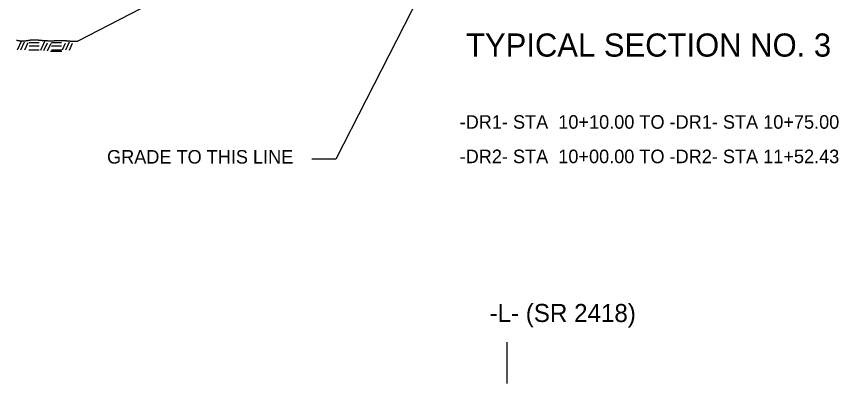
# Model space of a CAD drawing. Extents: x 1542177 to 1542464, y 45134 to 45344.
# Drawn here: x 1542275.51 to 1542311.92, y 45178.07 to 45194.34 of the extents above; entities that cross this region are included whole.
import ezdxf

# ---------------------------------------------------------------- set-up
doc = ezdxf.new("R2010")
doc.units = 0
for name, color, linetype in [('Default', 7, 'Continuous'), ('Old_Level_1', 7, 'Continuous'), ('Old_Level_2', 7, 'Continuous')]:
    doc.layers.add(name, color=color, linetype=linetype)

msp = doc.modelspace()

# ---------------------------------------------------------------- linework, layer by layer
at = {"layer": 'Default'}
for p, q in [((1542278.251, 45193.26), (1542289.419, 45199.047)), ((1542275.745, 45193.258), (1542275.554, 45192.844)), ((1542275.863, 45193.203), (1542275.698, 45192.854)), ((1542276.016, 45193.172), (1542275.868, 45192.853)), ((1542276.072, 45193.189), (1542276.519, 45193.189)), ((1542276.072, 45193.037), (1542276.52, 45193.036)), ((1542276.779, 45193.255), (1542276.582, 45192.834)), ((1542276.874, 45193.157), (1542276.718, 45192.819)), ((1542277.033, 45193.138), (1542276.877, 45192.8)), ((1542277.062, 45193.038), (1542277.513, 45193.037)), ((1542277.063, 45193.189), (1542277.513, 45193.188)), ((1542277.679, 45193.142), (1542277.544, 45192.853)), ((1542277.846, 45193.201), (1542277.682, 45192.846)), ((1542277.985, 45193.137), (1542277.843, 45192.833)), ((1542276.071, 45192.863), (1542276.519, 45192.863)), ((1542277.026, 45192.8), (1542277.521, 45192.8)), ((1542277.063, 45192.861), (1542277.512, 45192.862)), ((1542297.238, 45179.91), (1542297.238, 45178.068))]:
    msp.add_line(p, q, dxfattribs=at)
msp.add_open_spline([(1542275.515, 45193.287), (1542275.516, 45193.288), (1542275.516, 45193.289), (1542275.517, 45193.29), (1542275.52, 45193.291), (1542275.522, 45193.289), (1542275.524, 45193.289), (1542275.527, 45193.289), (1542275.529, 45193.29), (1542275.532, 45193.29), (1542275.534, 45193.29), (1542275.536, 45193.288), (1542275.538, 45193.288), (1542275.541, 45193.287), (1542275.543, 45193.286), (1542275.546, 45193.286), (1542275.548, 45193.285), (1542275.551, 45193.285), (1542275.553, 45193.284), (1542275.555, 45193.284), (1542275.557, 45193.283), (1542275.559, 45193.282), (1542275.562, 45193.282), (1542275.565, 45193.283), (1542275.568, 45193.282), (1542275.57, 45193.282), (1542275.572, 45193.281), (1542275.575, 45193.28), (1542275.577, 45193.28), (1542275.58, 45193.281), (1542275.582, 45193.281), (1542275.585, 45193.28), (1542275.587, 45193.279), (1542275.59, 45193.279), (1542275.592, 45193.278), (1542275.594, 45193.277), (1542275.596, 45193.277), (1542275.599, 45193.276), (1542275.602, 45193.276), (1542275.604, 45193.276), (1542275.606, 45193.275), (1542275.609, 45193.276), (1542275.611, 45193.275), (1542275.613, 45193.275), (1542275.616, 45193.274), (1542275.618, 45193.273), (1542275.621, 45193.273), (1542275.623, 45193.272), (1542275.626, 45193.272), (1542275.628, 45193.271), (1542275.63, 45193.272), (1542275.633, 45193.271), (1542275.635, 45193.271), (1542275.638, 45193.27), (1542275.64, 45193.269), (1542275.642, 45193.269), (1542275.644, 45193.268), (1542275.647, 45193.268), (1542275.65, 45193.267), (1542275.653, 45193.269), (1542275.657, 45193.268), (1542275.659, 45193.268), (1542275.661, 45193.266), (1542275.663, 45193.266), (1542275.667, 45193.266), (1542275.671, 45193.266), (1542275.675, 45193.266), (1542275.677, 45193.266), (1542275.679, 45193.267), (1542275.681, 45193.266), (1542275.685, 45193.266), (1542275.689, 45193.265), (1542275.692, 45193.265), (1542275.694, 45193.265), (1542275.697, 45193.264), (1542275.699, 45193.264), (1542275.702, 45193.264), (1542275.706, 45193.265), (1542275.709, 45193.265), (1542275.712, 45193.265), (1542275.715, 45193.265), (1542275.717, 45193.264), (1542275.721, 45193.264), (1542275.725, 45193.264), (1542275.728, 45193.264), (1542275.732, 45193.264), (1542275.735, 45193.264), (1542275.739, 45193.264), (1542275.741, 45193.264), (1542275.744, 45193.265), (1542275.746, 45193.265), (1542275.749, 45193.265), (1542275.751, 45193.264), (1542275.753, 45193.264), (1542275.757, 45193.264), (1542275.76, 45193.264), (1542275.763, 45193.265), (1542275.767, 45193.265), (1542275.771, 45193.265), (1542275.775, 45193.265), (1542275.777, 45193.265), (1542275.78, 45193.264), (1542275.782, 45193.264), (1542275.785, 45193.264), (1542275.789, 45193.264), (1542275.792, 45193.265), (1542275.795, 45193.265), (1542275.798, 45193.265), (1542275.801, 45193.264), (1542275.803, 45193.264), (1542275.805, 45193.263), (1542275.807, 45193.263), (1542275.809, 45193.263), (1542275.812, 45193.264), (1542275.814, 45193.264), (1542275.816, 45193.264), (1542275.818, 45193.264), (1542275.82, 45193.264), (1542275.823, 45193.264), (1542275.825, 45193.264), (1542275.827, 45193.264), (1542275.83, 45193.264), (1542275.832, 45193.264), (1542275.835, 45193.264), (1542275.838, 45193.264), (1542275.84, 45193.264), (1542275.843, 45193.264), (1542275.845, 45193.264), (1542275.847, 45193.264), (1542275.849, 45193.264), (1542275.851, 45193.263), (1542275.853, 45193.264), (1542275.856, 45193.264), (1542275.86, 45193.264), (1542275.864, 45193.264), (1542275.868, 45193.264), (1542275.87, 45193.264), (1542275.873, 45193.264), (1542275.875, 45193.264), (1542275.877, 45193.264), (1542275.878, 45193.264), (1542275.88, 45193.264), (1542275.884, 45193.264), (1542275.888, 45193.265), (1542275.892, 45193.266), (1542275.895, 45193.266), (1542275.897, 45193.266), (1542275.899, 45193.267), (1542275.903, 45193.267), (1542275.906, 45193.265), (1542275.909, 45193.266), (1542275.913, 45193.266), (1542275.918, 45193.268), (1542275.922, 45193.268), (1542275.925, 45193.268), (1542275.928, 45193.267), (1542275.932, 45193.268), (1542275.935, 45193.268), (1542275.939, 45193.269), (1542275.943, 45193.269), (1542275.946, 45193.27), (1542275.949, 45193.271), (1542275.952, 45193.272), (1542275.956, 45193.272), (1542275.96, 45193.271), (1542275.963, 45193.272), (1542275.966, 45193.272), (1542275.968, 45193.272), (1542275.97, 45193.273), (1542275.973, 45193.273), (1542275.975, 45193.274), (1542275.978, 45193.275), (1542275.982, 45193.276), (1542275.986, 45193.274), (1542275.99, 45193.275), (1542275.992, 45193.275), (1542275.994, 45193.276), (1542275.997, 45193.276), (1542275.999, 45193.277), (1542276.001, 45193.278), (1542276.004, 45193.278), (1542276.006, 45193.278), (1542276.008, 45193.278), (1542276.01, 45193.279), (1542276.016, 45193.279), (1542276.021, 45193.279), (1542276.027, 45193.28), (1542276.03, 45193.281), (1542276.032, 45193.281), (1542276.035, 45193.282), (1542276.037, 45193.283), (1542276.04, 45193.283), (1542276.042, 45193.284), (1542276.044, 45193.285), (1542276.047, 45193.283), (1542276.049, 45193.284), (1542276.053, 45193.284), (1542276.056, 45193.286), (1542276.06, 45193.287), (1542276.063, 45193.287), (1542276.065, 45193.287), (1542276.068, 45193.287), (1542276.071, 45193.288), (1542276.074, 45193.291), (1542276.077, 45193.291), (1542276.08, 45193.292), (1542276.082, 45193.291), (1542276.085, 45193.291), (1542276.087, 45193.292), (1542276.089, 45193.292), (1542276.092, 45193.293), (1542276.094, 45193.294), (1542276.096, 45193.294), (1542276.099, 45193.295), (1542276.102, 45193.296), (1542276.104, 45193.296), (1542276.107, 45193.297), (1542276.11, 45193.297), (1542276.114, 45193.297), (1542276.117, 45193.298), (1542276.12, 45193.298), (1542276.122, 45193.298), (1542276.125, 45193.298), (1542276.127, 45193.298), (1542276.128, 45193.3), (1542276.13, 45193.3), (1542276.133, 45193.3), (1542276.136, 45193.3), (1542276.139, 45193.3), (1542276.141, 45193.3), (1542276.144, 45193.3), (1542276.146, 45193.3), (1542276.149, 45193.3), (1542276.153, 45193.301), (1542276.157, 45193.301), (1542276.159, 45193.302), (1542276.162, 45193.301), (1542276.164, 45193.301), (1542276.166, 45193.302), (1542276.168, 45193.303), (1542276.17, 45193.304), (1542276.174, 45193.304), (1542276.178, 45193.303), (1542276.182, 45193.303), (1542276.184, 45193.303), (1542276.187, 45193.303), (1542276.189, 45193.304), (1542276.191, 45193.304), (1542276.193, 45193.305), (1542276.195, 45193.305), (1542276.198, 45193.305), (1542276.2, 45193.305), (1542276.203, 45193.305), (1542276.205, 45193.305), (1542276.207, 45193.305), (1542276.209, 45193.305), (1542276.212, 45193.305), (1542276.214, 45193.305), (1542276.217, 45193.305), (1542276.219, 45193.305), (1542276.221, 45193.305), (1542276.223, 45193.305), (1542276.226, 45193.305), (1542276.229, 45193.307), (1542276.232, 45193.307), (1542276.234, 45193.307), (1542276.236, 45193.307), (1542276.238, 45193.307), (1542276.241, 45193.307), (1542276.243, 45193.307), (1542276.246, 45193.307), (1542276.248, 45193.307), (1542276.25, 45193.307), (1542276.251, 45193.307), (1542276.256, 45193.307), (1542276.26, 45193.307), (1542276.265, 45193.307), (1542276.269, 45193.307), (1542276.273, 45193.307), (1542276.277, 45193.307), (1542276.28, 45193.307), (1542276.282, 45193.306), (1542276.285, 45193.306), (1542276.292, 45193.306), (1542276.299, 45193.307), (1542276.306, 45193.307), (1542276.308, 45193.307), (1542276.311, 45193.307), (1542276.313, 45193.307), (1542276.315, 45193.307), (1542276.317, 45193.307), (1542276.32, 45193.307), (1542276.322, 45193.307), (1542276.324, 45193.307), (1542276.327, 45193.307), (1542276.329, 45193.307), (1542276.332, 45193.307), (1542276.335, 45193.307), (1542276.338, 45193.307), (1542276.342, 45193.307), (1542276.346, 45193.307), (1542276.348, 45193.306), (1542276.351, 45193.306), (1542276.354, 45193.306), (1542276.356, 45193.306), (1542276.358, 45193.307), (1542276.36, 45193.307), (1542276.363, 45193.307), (1542276.365, 45193.306), (1542276.367, 45193.306), (1542276.37, 45193.306), (1542276.372, 45193.307), (1542276.374, 45193.307), (1542276.377, 45193.307), (1542276.379, 45193.306), (1542276.381, 45193.306), (1542276.384, 45193.306), (1542276.386, 45193.307), (1542276.388, 45193.307), (1542276.39, 45193.307), (1542276.392, 45193.307), (1542276.394, 45193.307), (1542276.398, 45193.307), (1542276.402, 45193.306), (1542276.405, 45193.306), (1542276.408, 45193.305), (1542276.411, 45193.306), (1542276.413, 45193.305), (1542276.416, 45193.305), (1542276.418, 45193.305), (1542276.42, 45193.305), (1542276.423, 45193.305), (1542276.425, 45193.306), (1542276.427, 45193.305), (1542276.429, 45193.305), (1542276.432, 45193.303), (1542276.434, 45193.303), (1542276.437, 45193.303), (1542276.439, 45193.303), (1542276.442, 45193.303), (1542276.444, 45193.303), (1542276.447, 45193.303), (1542276.449, 45193.303), (1542276.453, 45193.303), (1542276.456, 45193.303), (1542276.46, 45193.303), (1542276.462, 45193.303), (1542276.465, 45193.302), (1542276.467, 45193.301), (1542276.469, 45193.301), (1542276.472, 45193.301), (1542276.474, 45193.301), (1542276.476, 45193.301), (1542276.478, 45193.3), (1542276.481, 45193.299), (1542276.496, 45193.297), (1542276.512, 45193.295), (1542276.527, 45193.294), (1542276.529, 45193.294), (1542276.532, 45193.294), (1542276.534, 45193.294), (1542276.537, 45193.294), (1542276.539, 45193.292), (1542276.542, 45193.292), (1542276.544, 45193.292), (1542276.546, 45193.292), (1542276.548, 45193.292), (1542276.55, 45193.292), (1542276.553, 45193.293), (1542276.555, 45193.293), (1542276.558, 45193.293), (1542276.56, 45193.291), (1542276.563, 45193.291), (1542276.565, 45193.291), (1542276.567, 45193.29), (1542276.57, 45193.29), (1542276.576, 45193.29), (1542276.582, 45193.291), (1542276.588, 45193.29), (1542276.59, 45193.29), (1542276.593, 45193.289), (1542276.595, 45193.289), (1542276.597, 45193.289), (1542276.6, 45193.289), (1542276.602, 45193.289), (1542276.605, 45193.288), (1542276.607, 45193.287), (1542276.61, 45193.287), (1542276.618, 45193.286), (1542276.626, 45193.286), (1542276.634, 45193.285), (1542276.641, 45193.285), (1542276.648, 45193.284), (1542276.655, 45193.284), (1542276.658, 45193.283), (1542276.662, 45193.283), (1542276.666, 45193.282), (1542276.67, 45193.281), (1542276.673, 45193.281), (1542276.677, 45193.28), (1542276.679, 45193.28), (1542276.682, 45193.28), (1542276.685, 45193.28), (1542276.687, 45193.28), (1542276.689, 45193.278), (1542276.692, 45193.278), (1542276.694, 45193.278), (1542276.696, 45193.278), (1542276.698, 45193.278), (1542276.7, 45193.278), (1542276.703, 45193.277), (1542276.705, 45193.277), (1542276.709, 45193.276), (1542276.713, 45193.276), (1542276.716, 45193.276), (1542276.719, 45193.276), (1542276.721, 45193.275), (1542276.724, 45193.275), (1542276.727, 45193.275), (1542276.729, 45193.274), (1542276.732, 45193.274), (1542276.738, 45193.274), (1542276.743, 45193.275), (1542276.749, 45193.275), (1542276.753, 45193.274), (1542276.756, 45193.273), (1542276.76, 45193.273), (1542276.762, 45193.273), (1542276.765, 45193.273), (1542276.767, 45193.273), (1542276.773, 45193.273), (1542276.778, 45193.273), (1542276.784, 45193.273), (1542276.786, 45193.273), (1542276.788, 45193.272), (1542276.791, 45193.272), (1542276.793, 45193.272), (1542276.795, 45193.271), (1542276.798, 45193.271), (1542276.8, 45193.271), (1542276.803, 45193.271), (1542276.805, 45193.271), (1542276.811, 45193.271), (1542276.817, 45193.271), (1542276.823, 45193.271), (1542276.826, 45193.271), (1542276.828, 45193.271), (1542276.83, 45193.271), (1542276.833, 45193.271), (1542276.835, 45193.269), (1542276.838, 45193.269), (1542276.841, 45193.269), (1542276.843, 45193.269), (1542276.845, 45193.269), (1542276.851, 45193.269), (1542276.857, 45193.269), (1542276.863, 45193.269), (1542276.865, 45193.269), (1542276.868, 45193.269), (1542276.87, 45193.269), (1542276.873, 45193.269), (1542276.875, 45193.269), (1542276.878, 45193.269), (1542276.884, 45193.269), (1542276.889, 45193.268), (1542276.894, 45193.267), (1542276.896, 45193.267), (1542276.899, 45193.267), (1542276.901, 45193.267), (1542276.906, 45193.267), (1542276.91, 45193.267), (1542276.915, 45193.267), (1542276.918, 45193.267), (1542276.921, 45193.268), (1542276.924, 45193.268), (1542276.93, 45193.267), (1542276.936, 45193.267), (1542276.942, 45193.267), (1542276.95, 45193.267), (1542276.959, 45193.267), (1542276.967, 45193.267), (1542276.973, 45193.267), (1542276.979, 45193.265), (1542276.985, 45193.265), (1542276.987, 45193.265), (1542276.989, 45193.265), (1542276.99, 45193.265), (1542276.993, 45193.265), (1542276.996, 45193.266), (1542276.998, 45193.266), (1542277.004, 45193.266), (1542277.011, 45193.265), (1542277.017, 45193.265), (1542277.019, 45193.265), (1542277.021, 45193.266), (1542277.023, 45193.266), (1542277.026, 45193.266), (1542277.028, 45193.263), (1542277.03, 45193.263), (1542277.033, 45193.263), (1542277.035, 45193.263), (1542277.038, 45193.263), (1542277.04, 45193.263), (1542277.042, 45193.263), (1542277.044, 45193.263), (1542277.047, 45193.263), (1542277.049, 45193.263), (1542277.052, 45193.263), (1542277.054, 45193.263), (1542277.056, 45193.262), (1542277.059, 45193.262), (1542277.062, 45193.261), (1542277.065, 45193.261), (1542277.067, 45193.261), (1542277.07, 45193.262), (1542277.072, 45193.262), (1542277.074, 45193.262), (1542277.076, 45193.262), (1542277.078, 45193.262), (1542277.081, 45193.262), (1542277.083, 45193.262), (1542277.086, 45193.262), (1542277.088, 45193.262), (1542277.091, 45193.262), (1542277.093, 45193.259), (1542277.095, 45193.259), (1542277.098, 45193.26), (1542277.101, 45193.26), (1542277.104, 45193.26), (1542277.107, 45193.261), (1542277.11, 45193.261), (1542277.113, 45193.261), (1542277.115, 45193.261), (1542277.117, 45193.261), (1542277.12, 45193.261), (1542277.122, 45193.261), (1542277.125, 45193.261), (1542277.127, 45193.261), (1542277.13, 45193.261), (1542277.133, 45193.26), (1542277.136, 45193.26), (1542277.139, 45193.26), (1542277.142, 45193.26), (1542277.145, 45193.26), (1542277.147, 45193.26), (1542277.149, 45193.26), (1542277.151, 45193.26), (1542277.154, 45193.26), (1542277.157, 45193.261), (1542277.159, 45193.262), (1542277.161, 45193.262), (1542277.163, 45193.263), (1542277.165, 45193.263), (1542277.168, 45193.264), (1542277.17, 45193.265), (1542277.173, 45193.266), (1542277.176, 45193.266), (1542277.18, 45193.267), (1542277.183, 45193.268), (1542277.186, 45193.268), (1542277.188, 45193.269), (1542277.191, 45193.269), (1542277.196, 45193.27), (1542277.202, 45193.27), (1542277.208, 45193.271), (1542277.212, 45193.271), (1542277.215, 45193.273), (1542277.219, 45193.274), (1542277.222, 45193.275), (1542277.224, 45193.275), (1542277.227, 45193.276), (1542277.233, 45193.277), (1542277.239, 45193.275), (1542277.244, 45193.276), (1542277.247, 45193.276), (1542277.249, 45193.278), (1542277.251, 45193.278), (1542277.257, 45193.278), (1542277.263, 45193.278), (1542277.269, 45193.278), (1542277.277, 45193.278), (1542277.286, 45193.278), (1542277.294, 45193.278), (1542277.3, 45193.278), (1542277.307, 45193.279), (1542277.313, 45193.28), (1542277.319, 45193.28), (1542277.324, 45193.279), (1542277.33, 45193.279), (1542277.333, 45193.279), (1542277.335, 45193.28), (1542277.337, 45193.28), (1542277.343, 45193.28), (1542277.348, 45193.279), (1542277.354, 45193.28), (1542277.357, 45193.28), (1542277.359, 45193.28), (1542277.362, 45193.28), (1542277.368, 45193.28), (1542277.374, 45193.279), (1542277.38, 45193.279), (1542277.382, 45193.279), (1542277.385, 45193.279), (1542277.387, 45193.279), (1542277.39, 45193.279), (1542277.393, 45193.279), (1542277.395, 45193.279), (1542277.401, 45193.279), (1542277.406, 45193.279), (1542277.411, 45193.279), (1542277.417, 45193.279), (1542277.424, 45193.279), (1542277.43, 45193.279), (1542277.433, 45193.279), (1542277.437, 45193.279), (1542277.44, 45193.28), (1542277.445, 45193.28), (1542277.45, 45193.279), (1542277.455, 45193.279), (1542277.458, 45193.279), (1542277.46, 45193.28), (1542277.463, 45193.28), (1542277.465, 45193.28), (1542277.467, 45193.279), (1542277.469, 45193.279), (1542277.472, 45193.279), (1542277.474, 45193.279), (1542277.477, 45193.279), (1542277.479, 45193.279), (1542277.481, 45193.279), (1542277.483, 45193.279), (1542277.487, 45193.279), (1542277.491, 45193.279), (1542277.495, 45193.279), (1542277.497, 45193.279), (1542277.499, 45193.279), (1542277.502, 45193.279), (1542277.504, 45193.28), (1542277.507, 45193.279), (1542277.509, 45193.279), (1542277.511, 45193.279), (1542277.513, 45193.279), (1542277.516, 45193.279), (1542277.518, 45193.279), (1542277.52, 45193.279), (1542277.522, 45193.279), (1542277.524, 45193.279), (1542277.526, 45193.279), (1542277.527, 45193.279), (1542277.53, 45193.279), (1542277.533, 45193.279), (1542277.536, 45193.279), (1542277.538, 45193.279), (1542277.541, 45193.279), (1542277.543, 45193.279), (1542277.546, 45193.279), (1542277.549, 45193.279), (1542277.552, 45193.279), (1542277.555, 45193.279), (1542277.559, 45193.279), (1542277.562, 45193.28), (1542277.567, 45193.28), (1542277.572, 45193.279), (1542277.577, 45193.279), (1542277.579, 45193.279), (1542277.581, 45193.279), (1542277.584, 45193.279), (1542277.586, 45193.279), (1542277.588, 45193.277), (1542277.591, 45193.277), (1542277.593, 45193.277), (1542277.595, 45193.277), (1542277.597, 45193.277), (1542277.606, 45193.277), (1542277.614, 45193.276), (1542277.622, 45193.276), (1542277.628, 45193.276), (1542277.634, 45193.276), (1542277.64, 45193.276), (1542277.643, 45193.276), (1542277.645, 45193.276), (1542277.647, 45193.276), (1542277.65, 45193.276), (1542277.652, 45193.275), (1542277.655, 45193.274), (1542277.657, 45193.274), (1542277.66, 45193.273), (1542277.662, 45193.272), (1542277.664, 45193.271), (1542277.667, 45193.272), (1542277.669, 45193.272), (1542277.671, 45193.271), (1542277.673, 45193.27), (1542277.676, 45193.27), (1542277.682, 45193.269), (1542277.688, 45193.271), (1542277.694, 45193.27), (1542277.698, 45193.27), (1542277.701, 45193.268), (1542277.704, 45193.268), (1542277.707, 45193.268), (1542277.71, 45193.268), (1542277.713, 45193.268), (1542277.716, 45193.268), (1542277.72, 45193.269), (1542277.723, 45193.269), (1542277.725, 45193.269), (1542277.727, 45193.267), (1542277.73, 45193.267), (1542277.735, 45193.266), (1542277.739, 45193.267), (1542277.744, 45193.266), (1542277.747, 45193.266), (1542277.749, 45193.265), (1542277.751, 45193.265), (1542277.754, 45193.265), (1542277.756, 45193.265), (1542277.758, 45193.265), (1542277.76, 45193.265), (1542277.762, 45193.265), (1542277.765, 45193.265), (1542277.77, 45193.265), (1542277.776, 45193.265), (1542277.782, 45193.265), (1542277.785, 45193.265), (1542277.787, 45193.264), (1542277.79, 45193.264), (1542277.793, 45193.263), (1542277.795, 45193.263), (1542277.798, 45193.263), (1542277.8, 45193.263), (1542277.803, 45193.263), (1542277.805, 45193.263), (1542277.808, 45193.263), (1542277.81, 45193.261), (1542277.812, 45193.261), (1542277.814, 45193.261), (1542277.816, 45193.261), (1542277.818, 45193.261), (1542277.821, 45193.261), (1542277.824, 45193.262), (1542277.826, 45193.262), (1542277.829, 45193.262), (1542277.831, 45193.262), (1542277.834, 45193.261), (1542277.836, 45193.261), (1542277.838, 45193.26), (1542277.841, 45193.259), (1542277.843, 45193.259), (1542277.845, 45193.259), (1542277.847, 45193.259), (1542277.849, 45193.26), (1542277.852, 45193.26), (1542277.855, 45193.26), (1542277.857, 45193.26), (1542277.859, 45193.258), (1542277.862, 45193.258), (1542277.865, 45193.257), (1542277.869, 45193.258), (1542277.872, 45193.257), (1542277.875, 45193.257), (1542277.877, 45193.256), (1542277.879, 45193.256), (1542277.883, 45193.256), (1542277.887, 45193.257), (1542277.89, 45193.257), (1542277.892, 45193.256), (1542277.894, 45193.255), (1542277.896, 45193.254), (1542277.9, 45193.253), (1542277.904, 45193.252), (1542277.907, 45193.252), (1542277.911, 45193.252), (1542277.914, 45193.253), (1542277.918, 45193.253), (1542277.921, 45193.253), (1542277.923, 45193.253), (1542277.926, 45193.253), (1542277.934, 45193.252), (1542277.942, 45193.251), (1542277.951, 45193.25), (1542277.954, 45193.25), (1542277.958, 45193.25), (1542277.961, 45193.25), (1542277.964, 45193.25), (1542277.966, 45193.249), (1542277.969, 45193.249), (1542277.971, 45193.249), (1542277.973, 45193.248), (1542277.975, 45193.248), (1542277.978, 45193.248), (1542277.981, 45193.249), (1542277.983, 45193.249), (1542277.987, 45193.248), (1542277.991, 45193.247), (1542277.994, 45193.247), (1542277.996, 45193.247), (1542277.998, 45193.247), (1542278, 45193.247), (1542278.003, 45193.247), (1542278.006, 45193.247), (1542278.008, 45193.247), (1542278.012, 45193.247), (1542278.015, 45193.246), (1542278.018, 45193.245), (1542278.021, 45193.245), (1542278.023, 45193.245), (1542278.025, 45193.245), (1542278.028, 45193.245), (1542278.031, 45193.246), (1542278.034, 45193.246), (1542278.037, 45193.245), (1542278.04, 45193.243), (1542278.044, 45193.243), (1542278.046, 45193.243), (1542278.048, 45193.243), (1542278.051, 45193.243), (1542278.053, 45193.243), (1542278.056, 45193.243), (1542278.059, 45193.243), (1542278.068, 45193.243), (1542278.077, 45193.242), (1542278.087, 45193.242), (1542278.092, 45193.242), (1542278.098, 45193.242), (1542278.104, 45193.242), (1542278.106, 45193.242), (1542278.109, 45193.242), (1542278.111, 45193.242), (1542278.114, 45193.242), (1542278.116, 45193.242), (1542278.118, 45193.242), (1542278.124, 45193.242), (1542278.13, 45193.241), (1542278.136, 45193.241), (1542278.139, 45193.241), (1542278.14, 45193.243), (1542278.142, 45193.243), (1542278.149, 45193.243), (1542278.156, 45193.243), (1542278.162, 45193.243), (1542278.164, 45193.243), (1542278.167, 45193.243), (1542278.169, 45193.243), (1542278.171, 45193.243), (1542278.173, 45193.245), (1542278.175, 45193.246), (1542278.181, 45193.246), (1542278.187, 45193.244), (1542278.193, 45193.246), (1542278.195, 45193.246), (1542278.197, 45193.246), (1542278.2, 45193.247), (1542278.202, 45193.248), (1542278.205, 45193.248), (1542278.207, 45193.249), (1542278.21, 45193.249), (1542278.212, 45193.25), (1542278.215, 45193.251), (1542278.219, 45193.251), (1542278.222, 45193.253), (1542278.226, 45193.254), (1542278.229, 45193.255), (1542278.231, 45193.254), (1542278.234, 45193.254), (1542278.236, 45193.255), (1542278.238, 45193.256), (1542278.241, 45193.257), (1542278.243, 45193.258), (1542278.245, 45193.259), (1542278.247, 45193.26), (1542278.249, 45193.26), (1542278.25, 45193.26), (1542278.251, 45193.26)], degree=3, dxfattribs=at)
at = {"layer": 'Old_Level_2'}
msp.add_lwpolyline([(1542295.03, 45198.554), (1542289.657, 45188.016), (1542288.595, 45188.015)], dxfattribs=at)

# ---------------------------------------------------------------- texts
at = {"layer": 'Default'}
for s, height, p in [('TYPICAL SECTION NO. 3', 1.02627, (1542295.427, 45192.561)), ('-DR1- STA  10+10.00 TO -DR1- STA 10+75.00', 0.6, (1542295.143, 45189.365)), ('-DR2- STA  10+00.00 TO -DR2- STA 11+52.43', 0.6, (1542295.143, 45187.838))]:
    msp.add_text(s, height=height, dxfattribs=at).set_placement(p)
msp.add_text('-L- (SR 2418)', height=0.8, rotation=359.9469, dxfattribs=at).set_placement((1542296.466, 45180.8))
at = {"layer": 'Old_Level_1'}
msp.add_text('GRADE TO THIS LINE ', height=0.6, dxfattribs=at).set_placement((1542279.528, 45187.82))

doc.saveas('drawing.dxf')
